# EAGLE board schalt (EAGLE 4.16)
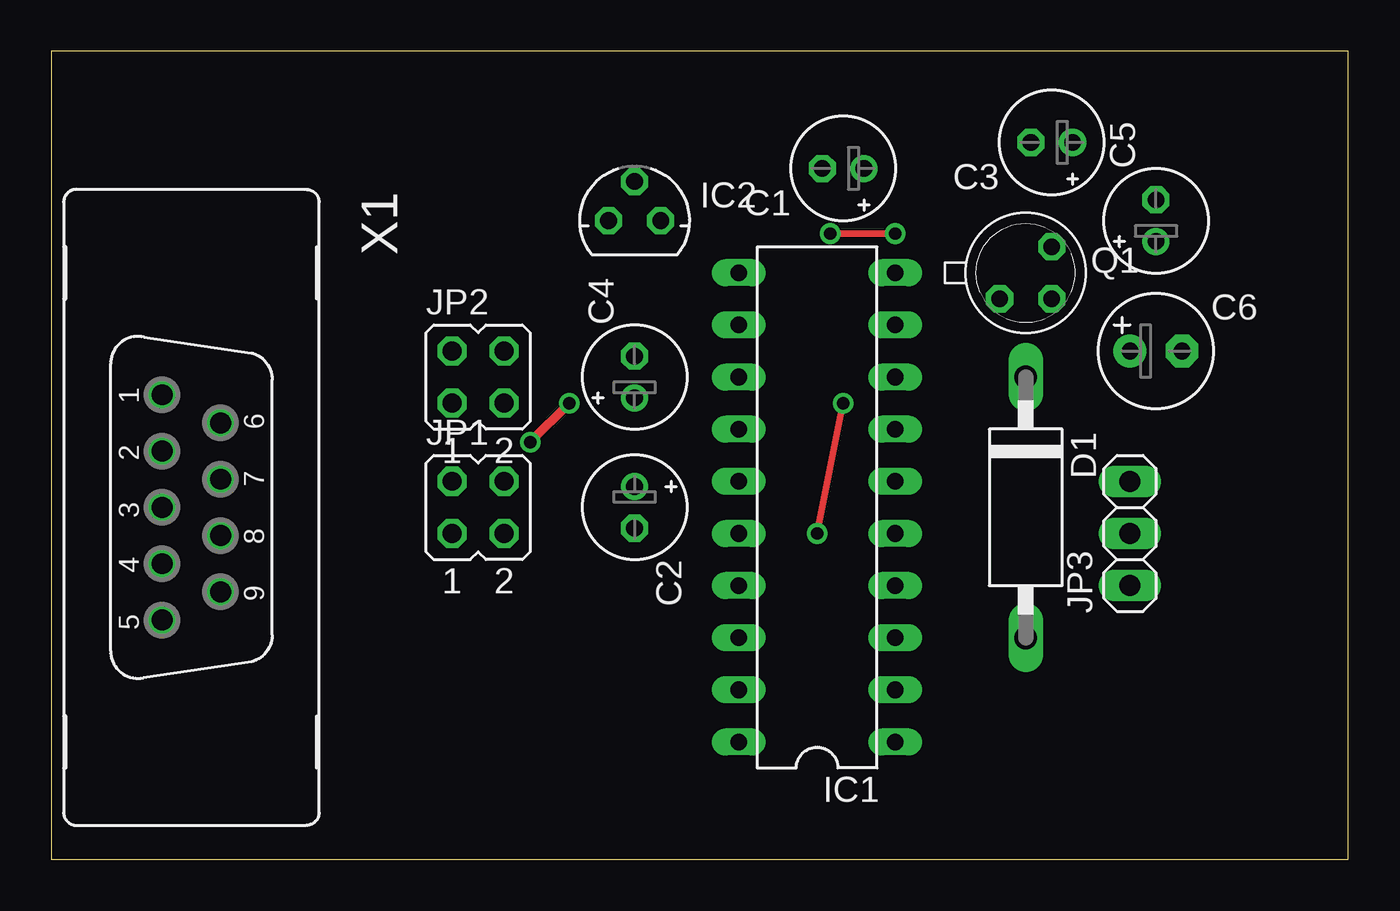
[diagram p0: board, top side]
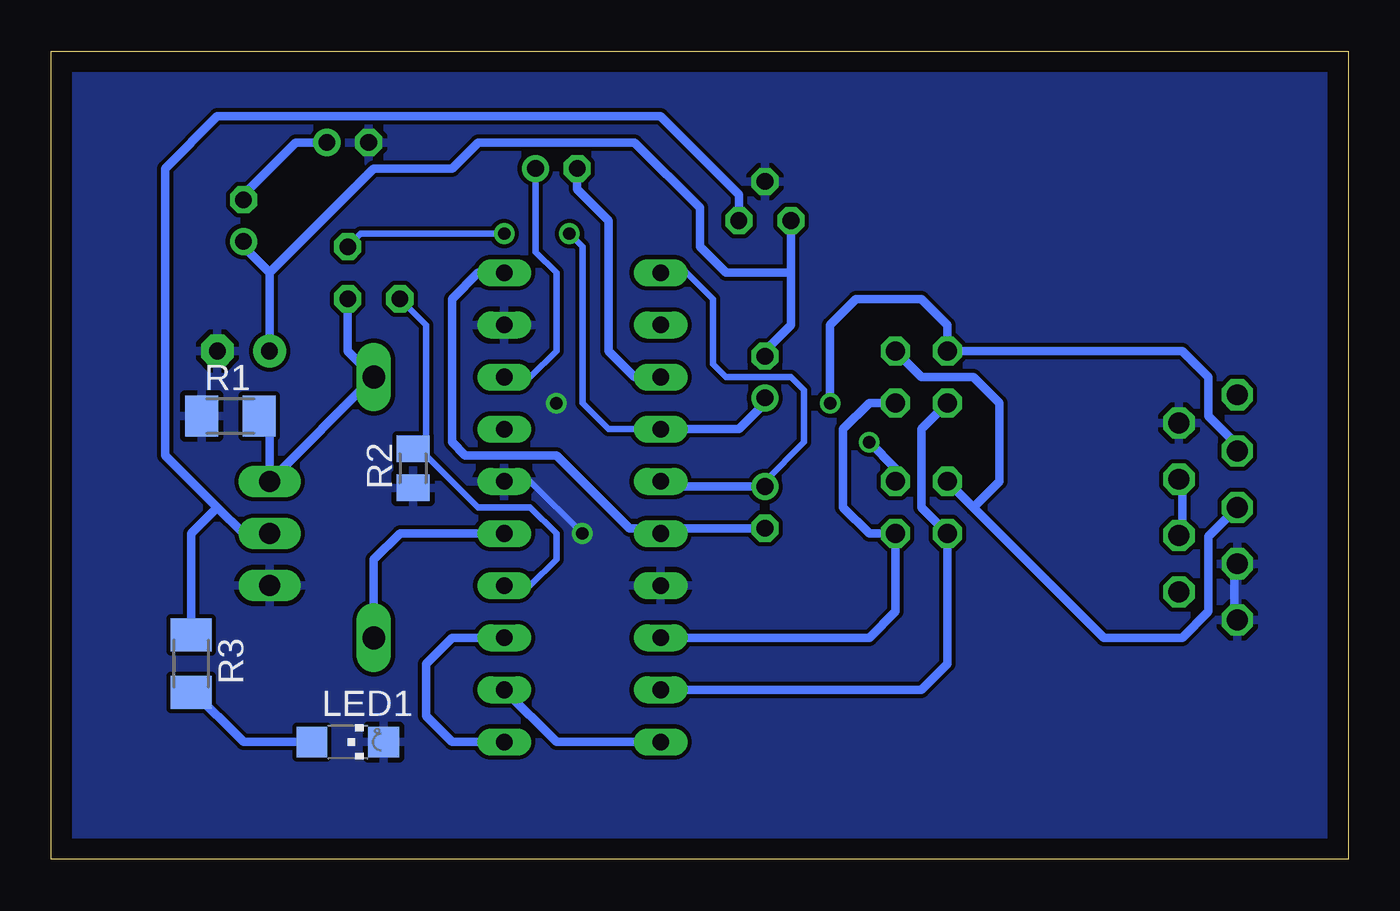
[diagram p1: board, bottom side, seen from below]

Size 63.17 x 39.36 mm. Coordinates in mm from the lower left corner, seen from the top.
Outline: 0,0 63.17,0 63.17,39.36 0,39.36 0,0
Copper layers (1*16): Top 0.035mm / dielectric 1.5mm / Bottom 0.035mm
Design rules "default": minimum track width 10mil, minimum drill 24mil, track to track 8mil, track to pad 8mil, pad to pad 8mil, via to via 8mil, smd to smd 8mil, copper to edge 40mil, drill to drill 8mil, minimum pad ring 10mil, minimum via ring 8mil, stop-mask expansion 4mil, vias tented up to drill 0mil, thermal gap 10mil

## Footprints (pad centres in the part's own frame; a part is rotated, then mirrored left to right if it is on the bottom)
E2-5 = drill 0.813 pad 1.27 round: + -1.016,0 | drill 0.813 pad 1.27 octagon: - 1.016,0
E2,5-6 = drill 0.813 pad 1.6 round: + -1.27,0 | drill 0.813 pad 1.6 octagon: - 1.27,0
DO15-12 = drill 1.118 long: A 6.35,0; C -6.35,0
DIL20 = drill 0.813 long: 1 -11.43,-3.81; 2 -8.89,-3.81; 3 -6.35,-3.81; 4 -3.81,-3.81; 5 -1.27,-3.81; 6 1.27,-3.81; 7 3.81,-3.81; 8 6.35,-3.81; 9 8.89,-3.81; 10 11.43,-3.81; 11 11.43,3.81; 12 8.89,3.81; 13 6.35,3.81; 14 3.81,3.81; 15 1.27,3.81; 16 -1.27,3.81; 17 -3.81,3.81; 18 -6.35,3.81; 19 -8.89,3.81; 20 -11.43,3.81
78LXX = drill 0.813 octagon: GND 0,1.905; IN 1.27,0; OUT -1.27,0
JP2Q = drill 0.914 octagon: 1 -1.27,-1.27; 2 -1.27,1.27; 3 1.27,-1.27; 4 1.27,1.27
1X03 = drill 1.016 long: 1 -2.54,0; 2 0,0; 3 2.54,0
CHIPLED_1206 = smd 1.5 x 1.5: A 0,-1.75; C 0,1.75
TO18 = drill 0.813 octagon: 1 -1.27,-1.27; 2 1.27,-1.27; 3 1.27,1.27
M1206 = smd 1.6 x 2: 1 -1.4,0; 2 1.4,0
M0805 = smd 1.3 x 1.6: 1 -0.95,0; 2 0.95,0
F09VB = drill 1.016 octagon: 1 -5.486,-1.422; 2 -2.743,-1.422; 3 0,-1.422; 4 2.743,-1.422; 5 5.486,-1.422; 6 -4.115,1.422; 7 -1.372,1.422; 8 1.372,1.422; 9 4.115,1.422

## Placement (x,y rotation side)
C1  [E2-5]  38.57,33.65 180 top
C2  [E2-5]  28.41,17.14 270 top
C3  [E2-5]  48.73,34.92 180 top
C4  [E2-5]  28.41,23.49 90 top
C5  [E2-5]  53.81,31.11 90 top
C6  10µF  [E2,5-6]  53.81,24.76 0 top
D1  1N5060GP  [DO15-12]  47.46,17.14 270 top
IC1  MAX233  [DIL20]  37.3,17.14 90 top
IC2  [78LXX]  28.41,31.11 0 top
JP1  [JP2Q]  20.79,17.14 0 top
JP2  [JP2Q]  20.79,23.49 0 top
JP3  [1X03]  52.54,15.87 90 top
LED1  SMD-LED 1206 BL  [CHIPLED_1206]  48.73,5.71 270 bottom
Q1  2N2222A  [TO18]  47.46,28.57 0 top
R1  10k  [M1206]  54.45,21.58 0 bottom
R2  [M0805]  45.55,19.04 90 bottom
R3  1k  [M1206]  56.35,9.52 270 bottom
X1  [F09VB]  6.82,17.14 270 top

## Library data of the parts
C1-C6 R1-R3 = rcl
D1 = diode
IC1 = maxim
IC2 = v-reg
JP1 JP2 = jumper
JP3 = pinhead
LED1 = led
Q1 = transistor-npn
X1 = con-subd

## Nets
+5V/1: IC1.7
DATA: D1.C JP3.3 Q1.2 R1.2
GND: C3.- C6.- IC1.6 IC1.9 IC1.17 IC2.GND JP3.1 LED1.C R1.1 R2.1 X1.4 X1.5 X1.6
N$1: D1.A IC1.5
N$2: IC2.IN JP3.2 R3.1
N$3: LED1.A R3.2
N$4: C1.- IC1.13
N$5: IC1.2 IC1.20
N$6: IC1.1 IC1.3
N$7: C1.+ IC1.8
N$8: C4.+ IC1.14 Q1.3
N$9: C3.+ C5.-
N$10: IC1.4 Q1.1 R2.2
N$11: C2.- IC1.10 IC1.16
N$12: C2.+ IC1.11 IC1.15
N$13: JP1.4 JP2.2 X1.2
N$14: JP1.2 JP2.4 X1.3
N$15: IC1.19 JP1.1 JP2.1
N$16: IC1.18 JP1.3 JP2.3
N$20: X1.7 X1.8
VCC: C4.- C5.+ C6.+ IC2.OUT

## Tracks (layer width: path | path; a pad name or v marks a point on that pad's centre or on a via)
DATA
  Bottom 0.406: Q1.2 48.73,24.76 D1.C JP3.3 52.54,21.58 R1.2
GND  (via drill 0.6)
  Top 0.305: v37.3,15.87 v38.57,22.22
  Bottom 0.305: IC1.6 39.84,18.41 v37.3,15.87
  Bottom 0.406: X1.5 5.55,11.65 5.55,14.4 X1.4
  pour Bottom: -3.34,81.91 -3.34,-5.72 109.69,-5.72 109.69,81.91
N$1
  Bottom 0.406: IC1.5 46.19,15.87 47.46,14.6 D1.A
N$2
  Bottom 0.406: IC2.IN 29.68,32.38 33.49,36.19 55.08,36.19 57.62,33.65 57.62,19.68 55.08,17.14 | 55.08,17.14 53.81,15.87 JP3.2 | R3.1 56.35,15.87 55.08,17.14
N$3
  Bottom 0.406: R3.2 56.35,8.25 53.81,5.71 LED1.A
N$4
  Bottom 0.406: IC1.13 34.76,23.49 36.03,24.76 36.03,31.11 37.55,32.63 C1.-
N$5
  Bottom 0.406: IC1.20 38.57,5.71 IC1.2
N$6
  Bottom 0.406: IC1.3 43.65,10.79 44.92,9.52 44.92,6.98 43.65,5.71 IC1.1
N$7
  Bottom 0.305: C1.+ 39.59,29.59 38.57,28.57 38.57,24.76 39.84,23.49 IC1.8
N$8  (via drill 0.6)
  Top 0.305: v37.94,30.47 v41.11,30.47
  Bottom 0.305: IC1.14 36.03,20.95 37.3,22.22 37.3,29.84 v37.94,30.47 | v41.11,30.47 48.09,30.47 Q1.3
  Bottom 0.406: C4.+ 28.41,22.22 29.68,20.95 IC1.14
N$9
  Bottom 0.406: C5.- 53.81,32.38 51.27,34.92 C3.+
N$10
  Bottom 0.305: 44.92,19.99 R2.2 | 44.92,19.99 44.92,26.03 Q1.1 | 44.92,19.99 44.92,19.68 42.38,17.14 39.84,17.14 38.57,15.87 38.57,14.6 39.84,13.33 IC1.4
N$11
  Bottom 0.406: C2.- 33.24,16.12 | 33.24,16.12 IC1.16 | 33.24,16.12 35.01,16.12 38.57,19.68 43.02,19.68 43.65,20.31 43.65,27.3 42.38,28.57 IC1.10
N$12
  Bottom 0.305: 28.41,18.41 26.5,20.31 26.5,22.86 27.14,23.49 30.31,23.49 30.95,24.12 30.95,27.3 32.22,28.57 IC1.11
  Bottom 0.406: IC1.15 33.24,18.16 C2.+ 28.41,18.41
N$13  (via drill 0.6)
  Top 0.406: v25.23,22.22 v23.33,20.31
  Bottom 0.406: X1.2 5.4,19.83 5.55,19.68 5.55,20.31 6.82,21.58 6.82,23.49 8.09,24.76 JP2.2 19.52,26.03 20.79,27.3 23.96,27.3 25.23,26.03 v25.23,22.22 | JP1.4 22.06,19.04 v23.33,20.31
N$14
  Bottom 0.406: X1.3 6.82,15.72 6.82,12.06 8.09,10.79 11.9,10.79 18.25,17.14 | 18.25,17.14 JP1.2 | JP2.4 20.79,23.49 18.25,23.49 16.98,22.22 16.98,18.41 18.25,17.14
N$15
  Bottom 0.406: IC1.19 20.79,8.25 19.52,9.52 JP1.1 20.79,17.14 20.79,20.95 JP2.1
N$16
  Bottom 0.406: IC1.18 23.33,10.79 22.06,12.06 JP1.3 23.33,15.87 24.6,17.14 24.6,20.95 23.33,22.22 JP2.3
N$20
  Bottom 0.406: X1.7 8.09,18.51 8.09,15.77 X1.8
VCC
  Bottom 0.406: C4.- 28.41,24.76 27.14,26.03 27.14,28.57 | 27.14,28.57 IC2.OUT | 52.54,27.3 C6.+ 52.54,28.57 | C5.+ 53.81,29.84 52.54,28.57 | 52.54,28.57 47.46,33.65 43.65,33.65 42.38,34.92 34.76,34.92 31.58,31.74 31.58,29.84 30.31,28.57 27.14,28.57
